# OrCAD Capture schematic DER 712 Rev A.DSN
size Custom; title: DER-712; rev: A
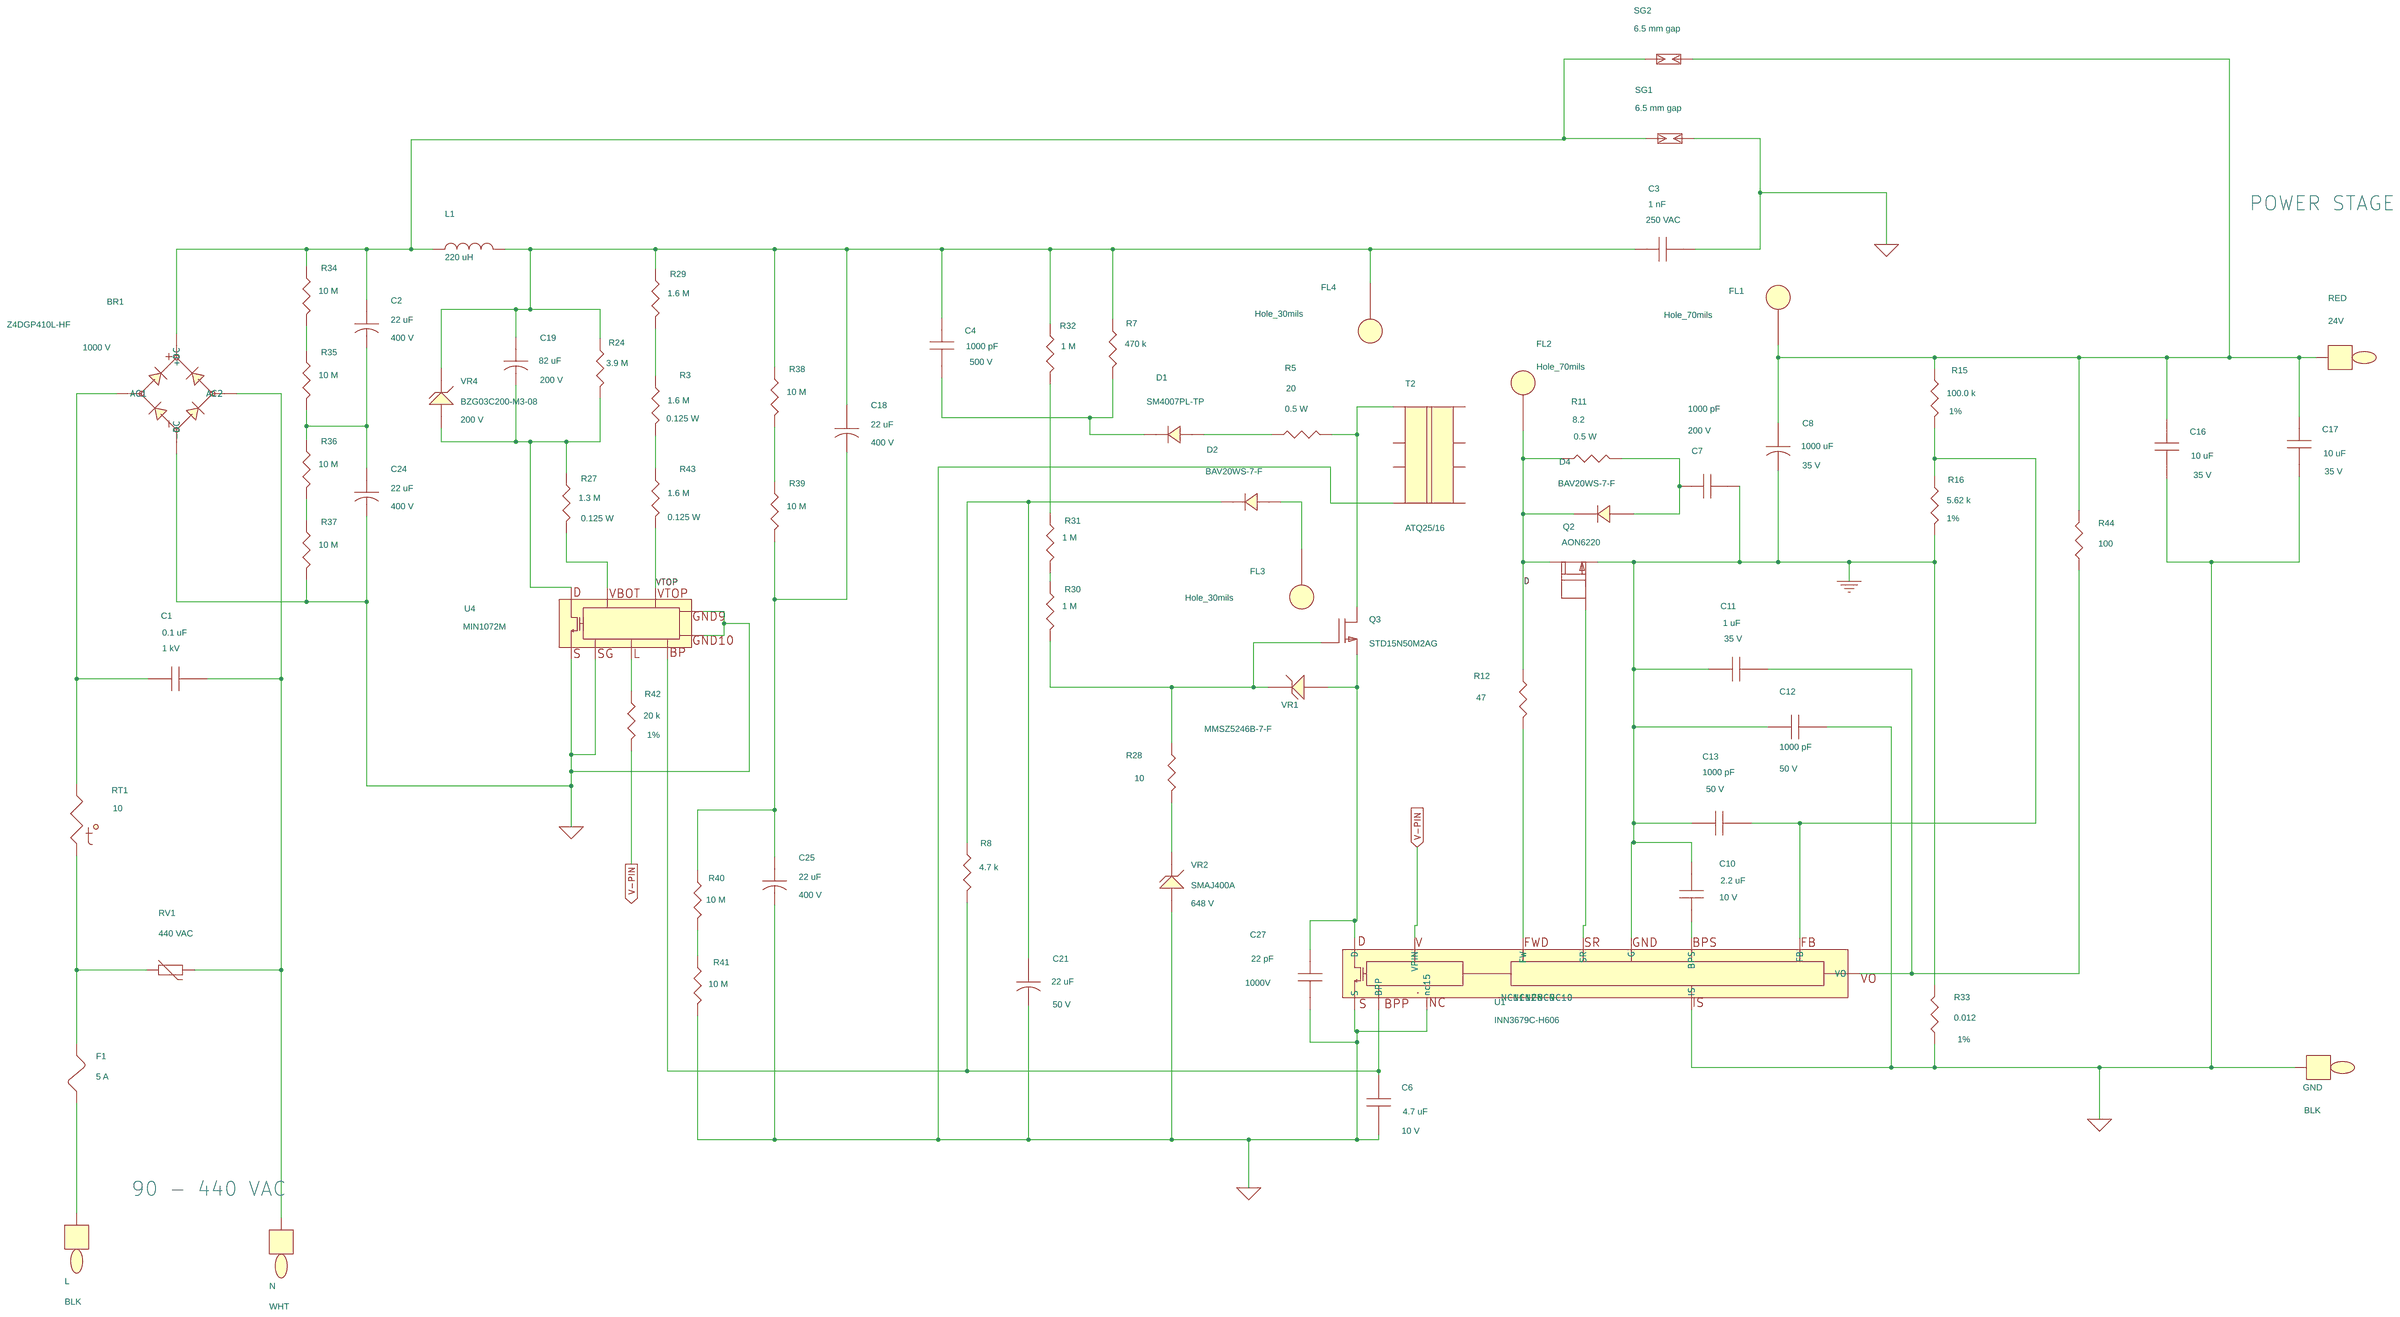
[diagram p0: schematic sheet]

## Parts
24V  RED  [pitpkeystone100x100]
BR1  Z4DGP410L-HF  [pi_sm_d_z4d]
C1  0.1 uF  [pi_np_cap_rad_17p5x10xLS15d040]
C2  22 uF  [pipolcapclyd320ls140030]
C3  1 nF  [pinpycaprad540x290ls400040]
C4  1000 pF  [pismc0805]
C6  4.7 uF  [pismc0805]
C7  1000 pF  [pismc0603]
C8  1000 uF  [pipolcapclyd10mmD30]
C10  2.2 uF  [pismc0805]
C11  1 uF  [pismc0603]
C12  1000 pF  [pismr0402]
C13  1000 pF  [pismr0402]
C16  10 uF  [pismc0805]
C17  10 uF  [pismc0805]
C18  22 uF  [pipolcapclyd320ls140030]
C19  82 uF  [pipolcapclyd500ls200040]
C21  22 uF  [pipolcapclyd200ls80030]
C24  22 uF  [pipolcapclyd320ls140030]
C25  22 uF  [pipolcapclyd320ls140030]
C27  22 pF  [pismc1206]
D1  SM4007PL-TP  [pi_sm_sod-123_12]
D2  BAV20WS-7-F  [pismdsod323]
D4  BAV20WS-7-F  [pismdsod323]
F1  5 A  [pi_rst_microfuse]
FL1  Hole_70mils  [pi_hole_70mil]
FL2  Hole_70mils  [pi_hole_70mil]
FL3  Hole_30mils  [pi_hole_30mil]
FL4  Hole_30mils  [pi_hole_30mil]
GND  BLK  [pitpkeystone100x100]
L  BLK  [pitpkeystone100x100]
L1  220 uH  [pichoke10p5x14p5d030]
N  WHT  [pitpkeystone100x100]
Q2  AON6220  [pismpqfn5x6b]
Q3  STD15N50M2AG  [pismddpak]
R3  1.6 M  [pi18wvresd80ls100d030]
R5  20  [pismr1210]
R7  470 k  [pismr1206]
R8  4.7 k  [pismr0603]
R11  8.2  [pismr1210]
R12  47  [pismr0603]
R15  100.0 k  [pismr0402]
R16  5.62 k  [pismr0402]
R24  3.9 M  [pismr1206]
R27  1.3 M  [pi18wvresd80ls100d030]
R28  10  [pi14wvresd100ls100d030]
R29  1.6 M  [pismr1206]
R30  1 M  [pismr1206]
R31  1 M  [pismr1206]
R32  1 M  [pismr1206]
R33  0.012  [pismr0805]
R34  10 M  [pismr1206]
R35  10 M  [pismr1206]
R36  10 M  [pismr1206]
R37  10 M  [pismr1206]
R38  10 M  [pismr1206]
R39  10 M  [pismr1206]
R40  10 M  [pismr1206]
R41  10 M  [pismr1206]
R42  20 k  [pismr0603]
R43  1.6 M  [pi18wvresd80ls100d030]
R44  100  [pismr0603]
RT1  10  [pi_rad770x220ls330d052]
RV1  440 VAC  [pidisc610x212ls295x95040]
SG1  6.5 mm gap  [PI_SPARK_GAP_6p5MM]
SG2  6.5 mm gap  [PI_SPARK_GAP_6p5MM]
T2  ATQ25/16  [pi_bobbin_ATQ25_H_8P]
U1  INN3679C-H606  [pi_ic_insop_24d]
U4  MIN1072M  [PI_SM_MinSOP16A_1]
VR1  MMSZ5246B-7-F  [pi_sm_sod-123_12]
VR2  SMAJ400A  [pismdo214ac12]
VR4  BZG03C200-M3-08  [pismdo214ac12]

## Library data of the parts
24V = TESTPOINT: Part Number: 35-00080-00
BR1 = DISCRETE_BRIDGE_+~~-: Disp_Voltage: 1000 V; Part Number: 15-01212-00
C1 = CAP_NP: ALT_SYMBOLS: pi_np_cap_rad_17p5x10xLS15d040H; Disp_Voltage: 1 kV; FPLIST: pi_np_cap_rad_17p5x10xLS15d040,pi_np_cap_rad_17p5x10xLS15d040H; Part Number: 20-01519-00; Voltage: 1000 V
C2 C18 C24 C25 = CAP_POL: ALT_SYMBOLS: pipolcapclyd320ls140030h630; Disp_Voltage: 400 V; FPLIST: pipolcapclyd320ls140030,pipolcapclyd320ls140030430h,pipolcapclyd320ls140030h630; Part Number: 20-01315-00; Voltage: 400 V
C3 = CAP_NP: ALT_SYMBOLS: pinpycaprad540x290ls400040h,pinpycaprad500x220ls400040; Disp_Voltage: 250 VAC; FPLIST: pinpycaprad540x290ls400040,pinpycaprad540x290ls400040h,pinpycaprad500x220ls400040; Part Number: 20-00375-00; Voltage: 250 VAC
C4 = CAP_NP: Disp_Voltage: 500 V; Part Number: 20-09036-00; Voltage: 500 V
C6 = CAP_NP: Disp_Voltage: 10 V; Part Number: 20-01487-00; Voltage: 10 V
C7 = CAP_NP: Disp_Voltage: 200 V; Part Number: 20-09194-00; Voltage: 200 V
C8 = CAP_POL: ALT_SYMBOLS: pipolcapclyd10x18mmD30H; Disp_Voltage: 35 V; FPLIST: pipolcapclyd10mmD30,pipolcapclyd10x18mmD30H; Part Number: 20-01528-00; Voltage: 35 V
C10 = CAP_NP: Disp_Voltage: 10 V; Part Number: 20-08747-00; Voltage: 10 V
C11 = CAP_NP: ALT_SYMBOLS: pismc0603_1; Disp_Voltage: 35 V; FPLIST: pismc0603,pismc0603_1; Part Number: 20-09172-00; Voltage: 35 V
C12 C13 = CAP_NP: ALT_SYMBOLS: pismr0402_1; Disp_Voltage: 50 V; FPLIST: pismr0402,pismr0402_1; Part Number: 20-09106-00; ROOM: 2; Voltage: 50 V
C16 C17 = CAP_NP: ALT_SYMBOLS: pismc0805_1; Disp_Voltage: 35 V; FPLIST: pismc0805,pismc0805_1; Part Number: 20-08720-00; Voltage: 35 V
C19 = CAP_POL: ALT_SYMBOLS: pipolcapclyd500ls200040850lh; Disp_Voltage: 200 V; FPLIST: pipolcapclyd500ls200040,pipolcapclyd500ls200040850lh; Part Number: 20-08997-00; Voltage: 200 V
C21 = CAP_POL: ALT_SYMBOLS: pipolcapclyd5p0x11mms2p0d30h; Disp_Voltage: 50 V; FPLIST: pipolcapclyd200ls80030,pipolcapclyd5p0x11mms2p0d30h; Part Number: 20-01498-00; Voltage: 50 V
C27 = CAP_NP: Disp_Voltage: 1000V; Part Number: 20-01144-00; Voltage: 1000 V
D1 = DIODE: Part Number: 15-01070-00
D2 D4 = DIODE: Part Number: 15-00712-00
F1 = FUSE: ALT_SYMBOLS: pirstmicrofusehoz; FPLIST: pi_rst_microfuse,pirstmicrofusehoz; Part Number: 40-00052-00
FL1 FL2 = FlyingLead: Part Number: 35-00282-00; ROOM: 2
FL3 FL4 = FlyingLead: Part Number: 35-00284-00; ROOM: 2
GND L = TESTPOINT: ALT_SYMBOLS: TP_TH_CR2_D1_1; FPLIST: pitpkeystone100x100,TP_TH_CR2_D1_1; Part Number: 35-00079-00
L1 = INDUCTOR: ALT_SYMBOLS: pichoke10p5x14p5d030H; FPLIST: pichoke10p5x14p5d030,pichoke10p5x14p5d030H; Part Number: 30-00529-00
N = TESTPOINT: Part Number: 35-00081-00
Q2 = FET_N_SGD_123_4_5678: Part Number: 50-00276-00
Q3 = FET_N_GDS: ALT_SYMBOLS: pi_sm_d_pak_1; FPLIST: pismddpak,pi_sm_d_pak_1; Part Number: 50-00301-00
R3 R43 = R: ALT_SYMBOLS: pi18wresd080ls300d030; Disp_Power: 0.125 W; FPLIST: pi18wvresd80ls100d030,pi18wresd080ls300d030; Part Number: 05-02414-00
R5 = R: Disp_Power: 0.5 W; Part Number: 05-06460-00
R7 = R: Part Number: 05-01416-00
R8 = R: Part Number: 05-01704-00
R11 = R: Disp_Power: 0.5 W; Part Number: 05-03465-00
R12 = R: ALT_SYMBOLS: pismr0603_1; Part Number: 05-01656-00; ROOM: 2
R15 = R: ALT_SYMBOLS: pismr0402_1; Disp_Tol: 1%; FPLIST: pismr0402,pismr0402_1; Part Number: 05-06039-00
R16 = R: Disp_Tol: 1%; Part Number: 05-05908-00
R24 = R: Part Number: 05-01435-00
R27 = R: ALT_SYMBOLS: pi18wresd080ls300d030; Disp_Power: 0.125 W; FPLIST: pi18wvresd80ls100d030,pi18wresd080ls300d030; Part Number: 05-02412-00
R28 = R: ALT_SYMBOLS: pi14wvresd100ls125d030,pi14wvresd100ls150d030,pi14wvresd100ls200d030,pi14wvresd100ls300d030,pi14wresd100ls400d030,pi14wresd100ls500d030; FPLIST: pi14wvresd100ls100d030,pi14wvresd100ls125d030,pi14wvresd100ls150d030,pi14wvresd100ls200d030,pi14wvresd100ls300d030,pi14wresd100ls400d030,pi14wresd100ls500d030; Part Number: 05-02459-00
R29 = R: Part Number: 05-01426-00
R30-R32 = R: Part Number: 05-01424-00
R33 = R: Disp_Tol: 1%; Part Number: 05-06519-00
R34-R41 = R: Part Number: 05-01445-00
R42 = R: Disp_Tol: 1%; Part Number: 05-03213-00
R44 = R: Part Number: 05-01664-00
RT1 = THERMISTOR: Part Number: 90-00019-00
RV1 = VARISTOR: Part Number: 85-00054-00
SG1 SG2 = SPARK_GAP: Part Number: 66-00360-00
T2 = BATQ25_8P_GENERIC: Part Number: 25-01167-00
U1 = Inno3EP_P15: Part Number: 10-01050-03
U4 = MinE-CAP: Part Number: 10-01091-00
VR1 = DIODE_ZENER: Part Number: 15-01092-00
VR2 = DIODE_ZENER: Disp_Voltage: 648 V; Part Number: 15-01700-00
VR4 = DIODE_ZENER: Disp_Voltage: 200 V; Part Number: 15-01701-00

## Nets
GND: C7.2 C8.2 C10.2 C11.1 C12.1 C13.1 Q2.1(S) R16.2 R33.2 U1.2(G)
GND_SIGNAL: C3.2 C12.2 C16.2 C17.2 GND.1 R33.1 SG1.2 U1.1(IS)
D: D4.1 FL2.1 Q2.5(D) R11.1 R12.1
NC8: U1.8(NC8)
NC9: U1.9(NC9)
NC10: U1.10(NC10)
NC11: U1.11(NC11)
NC12: U1.12(NC12)
P_GND: BR1.4(-DC) C6.2 C21.2 C24.2 C25.2 C27.2 R37.2 R41.2 T2.4 U1.15(nc15) U1.16(S) U4.3 U4.9 U4.10 U4.11 VR2.2
V-PIN: R42.2 U1.13(VPIN)
VTOP: R43.2 U4.8
N10806149: C6.1 R8.2 U1.14(BPP) U4.4
N10840366: BR1.1(+DC) C2.1 L1.1 R34.1 SG1.1 SG2.1
N10873526: R12.2 U1.7(FW)
N10896401: 24V.1 C8.1 C16.1 C17.1 FL1.1 R15.1 R44.2 SG2.2
N10897256: C13.2 R15.2 R16.1 U1.3(FB)
N10950053: C21.1 D2.1 R8.1
N10961861: C3.1 C4.1 C18.1 C19.1 FL4.1 L1.2 R7.1 R24.1 R29.1 R32.1 R38.1 VR4.1
N11099981: BR1.2(AC1) C1.1 RT1.1
N11100037: BR1.3(AC2) C1.2 N.1 RV1.2
N11139529: C4.2 D1.1 R7.2
N11156493: C7.1 D4.2 R11.2
N12473754: C19.2 R24.2 R27.1 U4.16 VR4.2
N12475155: C2.2 C24.1 R35.2 R36.1
N12496023: Q2.4(G) U1.5(SR)
N12509564: Q3.2(D) R5.2 T2.1
N12515315: D1.2 R5.1
N12525421: F1.1 L.1
N12527964: D2.2 FL3.1
N12537489: R27.2 U4.1
N12548420: F1.2 RT1.2 RV1.1
N12550156: C18.2 C25.1 R39.2 R40.1
N12551012: C27.1 Q3.3(S) U1.24(D) VR1.2
N12551028: Q3.1(G) R28.1 R30.2 VR1.1
N12554391: R30.1 R31.2
N12554414: R31.1 R32.2
N12556866: R34.2 R35.1
N12556885: R36.2 R37.1
N12557063: R38.2 R39.1
N12557132: R40.2 R41.1
N12568337: R42.1 U4.5
N12586127: R28.2 VR2.1
N12588091: R3.2 R43.1
N12588138: R3.1 R29.2
N12597786: C10.1 U1.4(BPS)
N12598687: C11.2 R44.1 U1.6(VO)

Not connected (* = marked no-connect by the designer): Q2 2(S2) 3(S3) 6(D6) 7(D7) 8(D8); T2 2 3 5 6 7 8

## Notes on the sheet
- POWER STAGE
- 90 - 440 VAC
